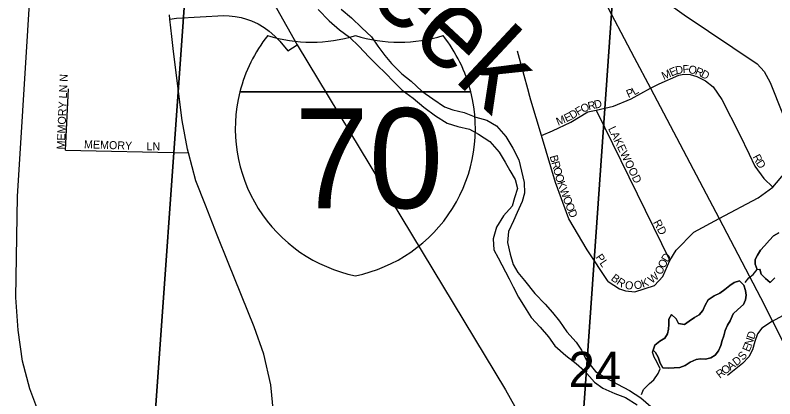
# Model space of a CAD drawing. Extents: x 0 to 34, y 0 to 22.
# Drawn here: x 3.162 to 4.06, y 19.621 to 20.075 of the extents above; entities that cross this region are included whole.
import ezdxf

# ---------------------------------------------------------------- set-up
doc = ezdxf.new("R2010")
doc.units = 0
for name, color, linetype in [('GM_X_City_Street', 7, 'Continuous'), ('GM_X_City_Street_Text', 7, 'Continuous'), ('GM_X_Interchange_Ramps', 7, 'Continuous'), ('GM_X_Interstate_Location', 7, 'Continuous'), ('GM_X_Interstate_Route', 7, 'Continuous'), ('GM_X_Interstate_Shield', 7, 'Continuous'), ('GM_X_Major_River', 7, 'Continuous'), ('GM_X_Major_River_Text', 7, 'Continuous'), ('GM_X_Minor_Lake', 7, 'Continuous'), ('GM_X_Rail_Line', 7, 'Continuous'), ('GM_X_Section', 7, 'Continuous'), ('GM_X_Section_Text', 7, 'Continuous'), ('GM_X_US_Route', 7, 'Continuous')]:
    doc.layers.add(name, color=color, linetype=linetype)

msp = doc.modelspace()

# ---------------------------------------------------------------- linework, layer by layer
at = {"layer": 'GM_X_City_Street'}
for points in [[(3.89385, 20.1247), (3.91149, 20.10595), (3.95307, 20.07583), (4.03928, 20.01785), (4.04759, 20.00871), (4.05475, 19.99578), (4.06941, 19.95891), (4.0743, 19.94751), (4.07996, 19.94255), (4.09432, 19.93157)], [(3.34719, 20.04995), (3.34487, 20.07052), (3.34427, 20.0757)], [(3.46739, 19.60501), (3.46436, 19.63765), (3.45587, 19.67398), (3.4444, 19.70648), (3.41372, 19.78274), (3.40074, 19.81483), (3.38695, 19.85033), (3.37554, 19.8794), (3.36675, 19.91224), (3.36551, 19.91685), (3.35934, 19.95057), (3.3492, 20.03217), (3.34719, 20.04995)], [(3.7692, 19.98368), (3.7559, 20.03283)], [(3.91335, 19.9888), (3.92348, 19.99387), (3.94663, 20.00414), (3.95269, 20.00562), (3.96033, 20.0051), (3.96813, 20.00263), (3.9784, 19.99743), (3.98758, 19.99031), (3.99771, 19.97538), (4.01852, 19.93458), (4.03003, 19.91061), (4.03688, 19.8965), (4.04742, 19.88185), (4.05783, 19.87158)], [(3.22126, 19.91551), (3.2247, 19.98791)], [(3.7842, 19.93285), (3.79727, 19.93855), (3.81891, 19.94873), (3.83899, 19.96087), (3.84913, 19.96279), (3.86939, 19.96744), (3.89035, 19.97607), (3.91335, 19.9888)], [(3.86339, 19.7603), (3.8385, 19.79758), (3.81664, 19.8341), (3.80086, 19.87743), (3.7842, 19.93285), (3.77162, 19.9747), (3.76923, 19.98356), (3.7692, 19.98368)], [(3.84913, 19.96279), (3.93624, 19.78477)], [(3.22126, 19.91551), (3.36675, 19.91224)], [(3.86339, 19.7603), (3.87663, 19.75153), (3.88382, 19.74923), (3.8948, 19.74805), (3.91794, 19.75519), (3.92783, 19.76616), (3.93624, 19.78477), (3.94346, 19.79724), (3.96443, 19.81845), (3.99442, 19.8346), (4.04058, 19.85912), (4.05783, 19.87158), (4.07297, 19.88943)], [(4.05769, 19.71328), (4.11165, 19.74258), (4.12507, 19.75394), (4.13587, 19.77041), (4.14768, 19.78898), (4.15177, 19.79663), (4.15315, 19.79921)], [(4.05769, 19.71328), (4.04496, 19.70492), (4.04002, 19.69821), (4.03661, 19.68931), (4.03414, 19.67945), (4.02945, 19.67093), (4.02195, 19.66301), (4.00437, 19.64899)]]:
    msp.add_lwpolyline(points, dxfattribs=at)
at = {"layer": 'GM_X_Interchange_Ramps'}
msp.add_lwpolyline([(3.34487, 20.07052), (3.35243, 20.07154), (3.40878, 20.07479), (3.41496, 20.07458), (3.4221, 20.07378), (3.42904, 20.07241), (3.43544, 20.07062), (3.44136, 20.06848), (3.44915, 20.06488), (3.45641, 20.06063), (3.46229, 20.05644), (3.46908, 20.05057), (3.47487, 20.04445), (3.48426, 20.03324), (3.49544, 20.04006)], dxfattribs=at)
at = {"layer": 'GM_X_Interstate_Route'}
msp.add_lwpolyline([(3.40982, 20.31645), (3.41048, 20.29227), (3.41081, 20.25146), (3.41642, 20.21556), (3.4256, 20.17846), (3.43426, 20.15803), (3.43941, 20.146), (3.4467, 20.13029), (3.45848, 20.10561), (3.49544, 20.04006), (3.74165, 19.63209), (3.85961, 19.42144), (3.94621, 19.29429), (3.9931, 19.25309), (4.01013, 19.24202), (4.02755, 19.23284)], dxfattribs=at)
at = {"layer": 'GM_X_Interstate_Shield'}
for p, q in [((3.42758, 19.98444), (3.70083, 19.98444)), ((3.70083, 19.98444), (3.42758, 19.98444)), ((3.70083, 19.98444), (3.42758, 19.98444))]:
    msp.add_line(p, q, dxfattribs=at)
for centre, start, end in [((3.59972, 19.9409), 141.66896, 165.80665), ((3.51232, 20.22084), 253.00908, 286.99093), ((3.61609, 20.22084), 253.00908, 286.99093), ((3.52869, 19.9409), 14.19335, 38.33104), ((3.59972, 19.9409), 165.80665, 258.46304), ((3.52869, 19.9409), 281.53696, 14.19335)]:
    msp.add_arc(centre, 0.17756, start, end, dxfattribs=at)
at = {"layer": 'GM_X_Major_River'}
for points in [[(3.52007, 20.08207), (3.53332, 20.06842), (3.54543, 20.0578), (3.55717, 20.04908), (3.56852, 20.03809), (3.58026, 20.02596), (3.5901, 20.0161), (3.59995, 20.00662), (3.60978, 19.99638), (3.61963, 19.98652), (3.6325, 19.97705), (3.64499, 19.96643), (3.659, 19.9562), (3.67263, 19.94748), (3.6855, 19.94369), (3.69913, 19.94029), (3.70973, 19.9346), (3.72336, 19.92588), (3.73434, 19.91299), (3.74153, 19.90124), (3.74683, 19.89138), (3.75326, 19.88076), (3.75591, 19.87014), (3.7525, 19.85914), (3.74984, 19.84927), (3.73924, 19.83789), (3.73129, 19.8246), (3.72712, 19.81057), (3.72787, 19.79767), (3.73317, 19.78819), (3.74604, 19.76316), (3.75096, 19.75368), (3.75701, 19.74154), (3.7661, 19.72713), (3.77215, 19.71765), (3.78275, 19.7059), (3.79259, 19.69452), (3.80016, 19.68391)], [(3.54733, 20.08246), (3.55945, 20.07222), (3.57194, 20.06047), (3.5833, 20.04948), (3.59086, 20.03848), (3.59919, 20.02748), (3.60676, 20.018), (3.61925, 20.00587), (3.63023, 19.99715), (3.64273, 19.9854), (3.65597, 19.9763), (3.6696, 19.96683), (3.67945, 19.96342), (3.6927, 19.96001), (3.70671, 19.95471), (3.71958, 19.95092), (3.73132, 19.94448), (3.74229, 19.93159), (3.75062, 19.91793), (3.75743, 19.9039), (3.76084, 19.89063), (3.76386, 19.87735), (3.76424, 19.86483), (3.76158, 19.85459), (3.75552, 19.84169), (3.75136, 19.83182), (3.74529, 19.8193), (3.74416, 19.8064), (3.74718, 19.79237), (3.75097, 19.78023), (3.75626, 19.77075), (3.76421, 19.76127), (3.77633, 19.74573), (3.78882, 19.73321), (3.79752, 19.72336), (3.80547, 19.71312), (3.81418, 19.7006), (3.82553, 19.68847), (3.83159, 19.67899), (3.83727, 19.66723), (3.84824, 19.65358), (3.86112, 19.64562), (3.87437, 19.6388), (3.88837, 19.63122), (3.902, 19.62251), (3.91374, 19.61227)], [(3.80016, 19.68391), (3.81303, 19.67253), (3.82553, 19.66306), (3.83537, 19.65434), (3.84711, 19.64106), (3.85695, 19.63386), (3.87095, 19.62742), (3.88383, 19.62288), (3.89746, 19.61416)]]:
    msp.add_lwpolyline(points, dxfattribs=at)
at = {"layer": 'GM_X_Minor_Lake'}
for points in [[(4.02535, 19.75905), (4.02953, 19.76438), (4.03486, 19.76858), (4.03942, 19.7743), (4.03714, 19.78077), (4.03714, 19.78611), (4.0398, 19.79145), (4.04323, 19.79717), (4.04817, 19.8025), (4.05388, 19.80899), (4.05882, 19.81433), (4.06491, 19.81777)], [(4.06491, 19.81777), (4.05882, 19.81433), (4.05388, 19.80899), (4.04817, 19.8025), (4.04323, 19.79717), (4.0398, 19.79145), (4.03714, 19.78611), (4.03714, 19.78077), (4.03942, 19.7743)], [(4.03942, 19.7743), (4.04247, 19.77469)], [(4.04247, 19.77469), (4.04437, 19.76898), (4.04932, 19.76365), (4.05503, 19.75909), (4.06035, 19.76443)], [(4.06035, 19.76443), (4.05503, 19.75909), (4.04932, 19.76365), (4.04437, 19.76898), (4.04247, 19.77469)], [(3.90245, 19.62631), (3.90512, 19.63241), (3.91196, 19.63927), (3.91729, 19.64385), (3.92224, 19.6511), (3.9249, 19.65681), (3.92071, 19.66519), (3.91767, 19.67052), (3.91577, 19.67661), (3.91843, 19.68461), (3.92452, 19.68958), (3.93022, 19.69301), (3.93327, 19.69835), (3.93441, 19.70368), (3.93479, 19.7094), (3.93517, 19.71549), (3.93821, 19.72121), (3.94354, 19.71589), (3.94658, 19.71056), (3.95343, 19.70904), (3.95914, 19.71324), (3.96523, 19.71744), (3.97094, 19.72049), (3.97512, 19.72584), (3.97778, 19.73193), (3.98159, 19.73841), (3.98844, 19.74299), (3.99529, 19.74643), (4.00138, 19.75063), (4.00708, 19.75521), (4.01241, 19.75903), (4.0185, 19.76094), (4.02382, 19.75562), (4.02573, 19.74952), (4.02649, 19.74381), (4.02573, 19.73848), (4.02345, 19.73276), (4.0166, 19.72703), (4.01127, 19.72169), (4.00747, 19.71369), (4.00442, 19.70835), (4.00176, 19.70225), (3.99986, 19.69577), (3.99796, 19.69044), (3.99644, 19.68434), (3.99377, 19.67824), (3.98997, 19.6729), (3.98464, 19.66985), (3.97817, 19.66831), (3.97247, 19.66869), (3.96714, 19.66792), (3.96029, 19.66448), (3.9542, 19.66067), (3.94811, 19.65837), (3.94126, 19.65798), (3.93403, 19.65759), (3.92794, 19.65796), (3.9249, 19.66329), (3.92223, 19.67052), (3.91919, 19.67624)], [(3.91919, 19.67624), (3.92223, 19.67052), (3.9249, 19.66329), (3.92794, 19.65796), (3.93403, 19.65759), (3.94126, 19.65798), (3.94811, 19.65837), (3.9542, 19.66067), (3.96029, 19.66448), (3.96714, 19.66792), (3.97247, 19.66869), (3.97817, 19.66831), (3.98464, 19.66985), (3.98997, 19.6729), (3.99377, 19.67824), (3.99644, 19.68434), (3.99796, 19.69044), (3.99986, 19.69577), (4.00176, 19.70225), (4.00442, 19.70835), (4.00747, 19.71369), (4.01127, 19.72169), (4.0166, 19.72703), (4.02345, 19.73276), (4.02573, 19.73848), (4.02649, 19.74381), (4.02573, 19.74952), (4.02382, 19.75562), (4.0185, 19.76094), (4.01241, 19.75903), (4.00708, 19.75521), (4.00138, 19.75063), (3.99529, 19.74643), (3.98844, 19.74299), (3.98159, 19.73841), (3.97778, 19.73193), (3.97512, 19.72584), (3.97094, 19.72049), (3.96523, 19.71744), (3.95914, 19.71324), (3.95343, 19.70904), (3.94658, 19.71056), (3.94354, 19.71589), (3.93821, 19.72121), (3.93517, 19.71549), (3.93479, 19.7094), (3.93441, 19.70368), (3.93327, 19.69835), (3.93022, 19.69301), (3.92452, 19.68958), (3.91843, 19.68461), (3.91646, 19.67869)], [(3.91646, 19.67869), (3.91919, 19.67624)]]:
    msp.add_lwpolyline(points, dxfattribs=at)
at = {"layer": 'GM_X_Rail_Line'}
msp.add_lwpolyline([(3.24228, 18.42761), (3.26853, 18.74288), (3.31378, 19.28503), (3.31089, 19.33131), (3.30511, 19.36506), (3.29355, 19.39591), (3.28103, 19.43351), (3.24731, 19.49618), (3.20203, 19.5791), (3.18855, 19.60803), (3.17892, 19.63309), (3.17025, 19.66588), (3.16543, 19.70251), (3.16255, 19.74108), (3.16448, 19.86064), (3.19533, 20.35523), (3.21268, 20.65312), (3.21364, 20.71674), (3.21171, 20.76398), (3.20409, 20.80854), (3.19954, 20.83827)], dxfattribs=at)
at = {"layer": 'GM_X_Section'}
for points in [[(3.37876, 20.32228), (3.30645, 19.30967), (2.80475, 19.34047), (2.87497, 20.35724)], [(3.88174, 20.28496), (3.81078, 19.27405), (3.30645, 19.30967), (3.37876, 20.32228)], [(4.3834, 20.24774), (4.31376, 19.23853), (3.81078, 19.27405), (3.88174, 20.28496)]]:
    msp.add_lwpolyline(points, close=True, dxfattribs=at)
at = {"layer": 'GM_X_US_Route'}
msp.add_lwpolyline([(3.75339, 20.29307), (3.75573, 20.28761), (3.7826, 20.23519), (3.80434, 20.19504), (3.82543, 20.15588), (3.85488, 20.09973), (3.89404, 20.02537), (3.91335, 19.9888), (3.99442, 19.8346), (4.0436, 19.74101), (4.05769, 19.71328), (4.06999, 19.68923), (4.07628, 19.67708)], dxfattribs=at)

# ---------------------------------------------------------------- texts
at = {"layer": 'GM_X_City_Street_Text'}
for s, height, rotation, p in [('M', 0.00947, 23.63146, (3.9289, 19.99851)), ('E', 0.00947, 23.63966, (3.93807, 20.00252)), ('D', 0.00947, 11.72996, (3.94368, 20.00504)), ('F', 0.00947, 2.37798, (3.95143, 20.00668)), ('O', 0.00947, 348.73722, (3.9575, 20.007)), ('R', 0.00947, 337.28299, (3.9652, 20.00552)), ('MEMORY LN N', 0.0094697, 87.66173, (3.22037, 19.91614)), ('D', 0.00947, 332.95603, (3.97194, 20.0027)), ('P', 0.00947, 23.7905, (3.88713, 19.97709)), ('L', 0.00947, 29.41532, (3.89412, 19.98023)), ('D', 0.00947, 13.7693, (3.84779, 19.96449)), ('F', 0.00947, 30.68724, (3.8277, 19.95614)), ('O', 0.00947, 25.36281, (3.83323, 19.95943)), ('R', 0.00947, 12.41026, (3.84022, 19.96282)), ('E', 0.00947, 26.01592, (3.81379, 19.94847)), ('D', 0.00947, 31.13839, (3.82059, 19.95184)), ('M', 0.00947, 22.57924, (3.80399, 19.94438)), ('LAKEWOOD', 0.00947, 295.92406, (3.86292, 19.94101)), ('MEMORY', 0.00947, 358.17922, (3.24305, 19.91784)), ('LN', 0.00947, 0.00001, (3.31716, 19.91534)), ('B', 0.00947, 285.56181, (3.79387, 19.90821)), ('R', 0.00947, 297.54252, (4.03376, 19.90765)), ('D', 0.00947, 301.75877, (4.0376, 19.90035)), ('R', 0.00947, 285.5512, (3.79588, 19.90098)), ('O', 0.00947, 285.5647, (3.7979, 19.89375)), ('O', 0.00947, 286.47607, (3.80017, 19.88557)), ('K', 0.00947, 289.61002, (3.80272, 19.87704)), ('W', 0.00947, 290.58626, (3.80558, 19.86903)), ('O', 0.00947, 290.59467, (3.80938, 19.85889)), ('O', 0.00947, 290.59187, (3.81232, 19.85108)), ('D', 0.00947, 292.63193, (3.81538, 19.84294)), ('RD', 0.00947, 297.89137, (3.91623, 19.83023)), ('PL', 0.00947, 304.69866, (3.84778, 19.78874)), ('D', 0.00947, 59.89458, (3.93351, 19.78242)), ('O', 0.00947, 62.37233, (3.92603, 19.76724)), ('O', 0.00947, 65.09335, (3.9301, 19.77506)), ('B', 0.00947, 322.66386, (3.86578, 19.76244)), ('W', 0.00947, 38.68166, (3.91487, 19.75719)), ('R', 0.00947, 326.38913, (3.87229, 19.7575)), ('O', 0.00947, 349.96786, (3.88246, 19.75178)), ('O', 0.00947, 12.7207, (3.89475, 19.75043)), ('K', 0.00947, 20.47341, (3.90422, 19.75266)), ('D', 0.00947, 70.70789, (4.03558, 19.69093)), ('N', 0.00947, 71.96352, (4.03302, 19.68306)), ('E', 0.00947, 66.96241, (4.03009, 19.67608)), ('D', 0.00947, 38.43371, (4.01483, 19.65968)), ('S', 0.00947, 48.46823, (4.02267, 19.66611)), ('O', 0.00947, 36.87426, (4.00127, 19.64951)), ('A', 0.00947, 36.86697, (4.00793, 19.65451)), ('R', 0.00947, 36.88446, (3.99527, 19.64501))]:
    msp.add_text(s, height=height, rotation=rotation, dxfattribs=at).set_placement(p)
at = {"layer": 'GM_X_Interstate_Location'}
for s in ['-', '.', ',']:
    msp.add_text(s, height=0.000189, dxfattribs=at).set_placement((3.56418, 19.90889))
msp.add_text('70', height=0.000189, rotation=0.00001, dxfattribs=at).set_placement((3.52549, 19.86968))
at = {"layer": 'GM_X_Interstate_Shield'}
msp.add_text('70', height=0.118371, dxfattribs=at).set_placement((3.492, 19.84684))
at = {"layer": 'GM_X_Major_River_Text'}
msp.add_text('Creek', height=0.094705, rotation=316.99149, dxfattribs=at).set_placement((3.47864, 20.18603))
at = {"layer": 'GM_X_Section_Text'}
msp.add_text('24', height=0.041856, rotation=0.00001, dxfattribs=at).set_placement((3.81632, 19.63519))

doc.saveas('drawing.dxf')
